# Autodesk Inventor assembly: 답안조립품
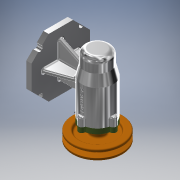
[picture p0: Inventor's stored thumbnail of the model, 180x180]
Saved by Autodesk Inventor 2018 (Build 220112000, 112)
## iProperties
Created: 2019-12
Part Number: 답안조립품
Document SubType Name: Assembly
Designer: Administrator
Author: Administrator
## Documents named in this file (12)
- C:\Users\Administrator\Desktop\491204V1070\답안조립품.iam
- C:\Users\Administrator\Desktop\491204V1070\V벨트풀리.ipt
- C:\Users\Administrator\Desktop\491204V1070\멈춤나사 M3.ipt
- C:\Users\Administrator\Desktop\491204V1070\베어링 6004.ipt
- C:\Users\Administrator\Desktop\491204V1070\베어링 51202.ipt
- C:\Users\Administrator\Desktop\491204V1070\본체.ipt
- C:\Users\Administrator\Desktop\491204V1070\볼트 M4.ipt
- C:\Users\Administrator\Desktop\491204V1070\어댑터슬리브.ipt
- C:\Users\Administrator\Desktop\491204V1070\오일 실.ipt
- C:\Users\Administrator\Desktop\491204V1070\축.ipt
- C:\Users\Administrator\Desktop\491204V1070\커버.ipt
- C:\Users\Administrator\Desktop\491204V1070\키 5 x 5 x 16.ipt
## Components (1 placed, 1 different names)
1. V벨트풀리:1
